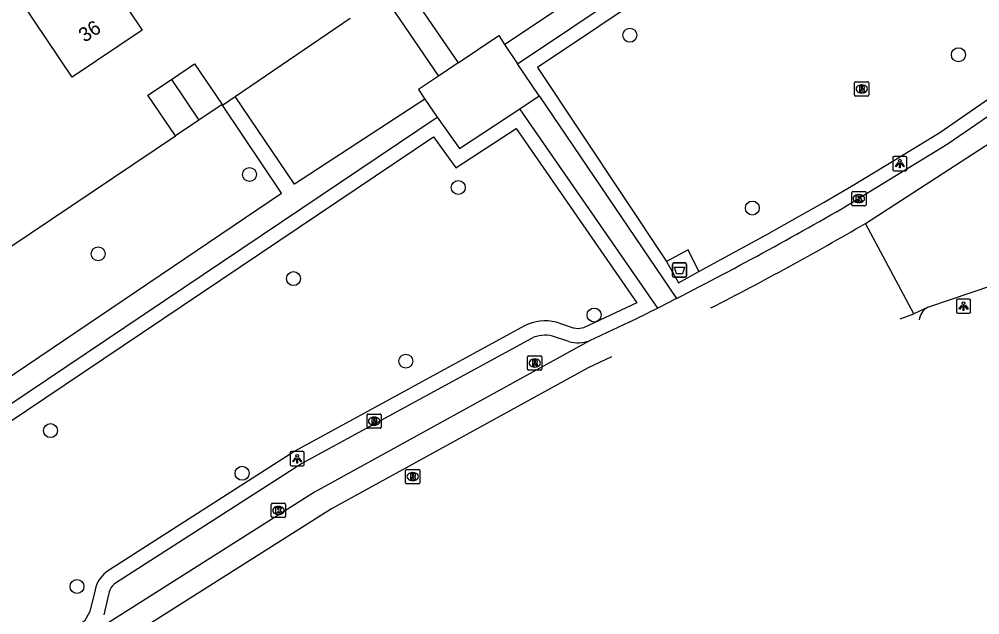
# Model space of a CAD drawing. Extents: x 158797 to 159887, y 384318 to 385255.
# Drawn here: x 159229 to 159296.2, y 384495.3 to 384536.9 of the extents above; entities that cross this region are included whole.
import ezdxf

# ---------------------------------------------------------------- set-up
doc = ezdxf.new("R2010")
doc.units = 0
for name, color, linetype in [('IMGEO_Afval_apart_plaats', 7, 'Continuous'), ('IMGEO_Boom', 7, 'Continuous'), ('IMGEO_Fietspad_gesloten', 7, 'Continuous'), ('IMGEO_Groenvoorziening', 7, 'Continuous'), ('IMGEO_Kolk', 7, 'Continuous'), ('IMGEO_Lichtpunt', 7, 'Continuous'), ('IMGEO_Pand', 7, 'Continuous'), ('IMGEO_Pand_nummerreeks', 7, 'Continuous'), ('IMGEO_Parkeervlak_open', 7, 'Continuous'), ('IMGEO_Rijbaan_lokaal_gesloten', 7, 'Continuous'), ('IMGEO_Rioolput', 7, 'Continuous'), ('IMGEO_Voetpad_gesloten', 7, 'Continuous'), ('IMGEO_Voetpad_open', 7, 'Continuous')]:
    doc.layers.add(name, color=color, linetype=linetype)

msp = doc.modelspace()

# ---------------------------------------------------------------- linework, layer by layer
at = {"layer": 'IMGEO_Afval_apart_plaats'}
for p, q in [((159274.727, 384518.982), (159274.727, 384519.782)), ((159274.727, 384519.782), (159274.727, 384518.982)), ((159274.827, 384519.882), (159275.617, 384519.882)), ((159275.617, 384519.882), (159274.827, 384519.882)), ((159275.717, 384519.782), (159275.717, 384518.982)), ((159275.717, 384518.982), (159275.717, 384519.782)), ((159275.617, 384518.882), (159274.827, 384518.882)), ((159274.827, 384518.882), (159275.617, 384518.882))]:
    msp.add_line(p, q, dxfattribs=at)
msp.add_lwpolyline([(159274.87, 384519.596), (159275.574, 384519.596), (159275.425, 384519.126), (159275.019, 384519.126), (159274.87, 384519.596)], dxfattribs=at)
for centre, start, end in [((159274.827, 384519.782), 90, 180), ((159274.827, 384519.782), 90, 180), ((159275.617, 384519.782), 0, 90), ((159275.617, 384519.782), 360, 90), ((159274.827, 384518.982), 180, 270), ((159274.827, 384518.982), 180, 270), ((159275.617, 384518.982), 270, 0), ((159275.617, 384518.982), 270, 0)]:
    msp.add_arc(centre, 0.1, start, end, dxfattribs=at)
at = {"layer": 'IMGEO_Boom'}
for centre in [(159271.748, 384535.8), (159294.74, 384534.44), (159245.143, 384526.065), (159259.751, 384525.162), (159280.321, 384523.725), (159234.56, 384520.524), (159248.224, 384518.788), (159269.249, 384516.243), (159256.083, 384513.017), (159231.225, 384508.163), (159244.626, 384505.181), (159233.077, 384497.268)]:
    msp.add_circle(centre, 0.489, dxfattribs=at)
at = {"layer": 'IMGEO_Fietspad_gesloten'}
msp.add_arc((159293.085, 384515.816), 1.088, 175.5911, 175.6123, dxfattribs=at)
at = {"layer": 'IMGEO_Groenvoorziening'}
for points in [[(159311.177, 384564.219), (159308.412, 384562.373), (159265.287, 384533.543), (159274.314, 384519.978)], [(159276.571, 384519.282), (159281.338, 384521.882), (159283.111, 384522.865), (159285.343, 384524.129), (159287.269, 384525.243), (159290.444, 384527.181), (159293.442, 384529.011), (159297.442, 384531.774), (159302.72, 384535.661), (159311.813, 384541.934), (159311.436, 384543.505), (159312.412, 384557.941)], [(159244.137, 384531.512), (159252.189, 384536.989)], [(159243.228, 384530.957), (159243.246, 384530.917)], [(159234.338, 384497.035), (159233.972, 384495.518), (159233.613, 384494.852), (159228.138, 384491.231), (159220.064, 384503.217), (159258.024, 384528.696), (159259.578, 384526.528), (159263.801, 384529.281), (159272.238, 384517.091), (159268.503, 384515.357), (159268.144, 384515.272), (159267.81, 384515.334), (159266.587, 384515.738)], [(159226.859, 384519.981), (159239.965, 384528.766)], [(159264.392, 384515.484), (159248.322, 384506.725), (159235.289, 384498.386)]]:
    msp.add_lwpolyline(points, dxfattribs=at)
for centre, radius, start, end in [((159265.818, 384512.772), 3.064, 75.46792, 117.73361), ((159236.374, 384496.612), 2.079, 121.44672, 168.26808)]:
    msp.add_arc(centre, radius, start, end, dxfattribs=at)
at = {"layer": 'IMGEO_Kolk'}
for p, q in [((159287.273, 384523.954), (159287.273, 384524.806)), ((159287.348, 384524.88), (159288.2, 384524.88)), ((159287.761, 384524.66), (159287.786, 384524.66)), ((159288.274, 384524.806), (159288.274, 384523.954)), ((159288.2, 384523.88), (159287.348, 384523.88)), ((159287.784, 384524.1), (159287.759, 384524.1)), ((159246.672, 384502.157), (159246.672, 384503.009)), ((159246.747, 384503.083), (159247.599, 384503.083)), ((159247.16, 384502.863), (159247.185, 384502.863)), ((159247.673, 384503.009), (159247.673, 384502.157)), ((159247.183, 384502.303), (159247.158, 384502.303)), ((159247.599, 384502.083), (159246.747, 384502.083))]:
    msp.add_line(p, q, dxfattribs=at)
for points in [[(159287.273, 384523.954), (159287.273, 384524.806)], [(159287.348, 384524.88), (159288.2, 384524.88)], [(159287.594, 384524.58), (159287.717, 384524.58), (159287.717, 384524.429), (159287.847, 384524.58), (159288.011, 384524.58), (159287.865, 384524.429), (159288.018, 384524.18), (159287.866, 384524.18), (159287.781, 384524.344), (159287.717, 384524.277), (159287.717, 384524.18), (159287.594, 384524.18), (159287.594, 384524.58)], [(159288.274, 384524.806), (159288.274, 384523.954)], [(159288.2, 384523.88), (159287.348, 384523.88)], [(159246.672, 384502.157), (159246.672, 384503.009)], [(159246.747, 384503.083), (159247.599, 384503.083)], [(159246.993, 384502.783), (159247.116, 384502.783), (159247.116, 384502.632), (159247.246, 384502.783), (159247.41, 384502.783), (159247.264, 384502.632), (159247.417, 384502.383), (159247.265, 384502.383), (159247.18, 384502.547), (159247.116, 384502.48), (159247.116, 384502.383), (159246.993, 384502.383), (159246.993, 384502.783)], [(159247.673, 384503.009), (159247.673, 384502.157)], [(159247.599, 384502.083), (159246.747, 384502.083)]]:
    msp.add_lwpolyline(points, dxfattribs=at)
for centre, start, end in [((159287.35, 384524.804), 91.55205, 178.44795), ((159287.35, 384524.804), 91.55205, 178.44795), ((159288.198, 384524.804), 1.55205, 88.44795), ((159288.198, 384524.804), 1.55205, 88.44795), ((159287.35, 384523.956), 181.55205, 268.44795), ((159287.35, 384523.956), 181.55205, 268.44795), ((159288.198, 384523.956), 271.55205, 358.44795), ((159288.198, 384523.956), 271.55205, 358.44795), ((159246.749, 384503.007), 91.55205, 178.44795), ((159246.749, 384503.007), 91.55205, 178.44795), ((159247.597, 384503.007), 1.55205, 88.44795), ((159247.597, 384503.007), 1.55205, 88.44795), ((159246.749, 384502.159), 181.55205, 268.44795), ((159246.749, 384502.159), 181.55205, 268.44795), ((159247.597, 384502.159), 271.55205, 358.44795), ((159247.597, 384502.159), 271.55205, 358.44795)]:
    msp.add_arc(centre, 0.0765, start, end, dxfattribs=at)
for centre, major_axis, ratio, start_param, end_param in [((159287.76, 384524.38), (-0.387, 0.002), 0.722429, 4.712389, 7.853982), ((159287.785, 384524.38), (-0.39, 0.002), 0.717154, 1.570796, 4.712389), ((159247.159, 384502.583), (-0.387, 0.002), 0.722429, 4.712389, 7.853982), ((159247.184, 384502.583), (-0.39, 0.002), 0.717154, 1.570796, 4.712389)]:
    msp.add_ellipse(centre, major_axis=major_axis, ratio=ratio, start_param=start_param, end_param=end_param, dxfattribs=at)
at = {"layer": 'IMGEO_Lichtpunt'}
for p, q in [((159290.139, 384527.233), (159290.139, 384526.426)), ((159290.139, 384527.233), (159290.139, 384526.426)), ((159291.041, 384527.328), (159290.233, 384527.328)), ((159291.041, 384527.328), (159290.233, 384527.328)), ((159291.135, 384526.426), (159291.135, 384527.233)), ((159291.135, 384526.426), (159291.135, 384527.233)), ((159290.233, 384526.332), (159291.041, 384526.332)), ((159290.233, 384526.332), (159291.041, 384526.332)), ((159294.599, 384517.266), (159294.599, 384516.459)), ((159294.599, 384517.266), (159294.599, 384516.459)), ((159295.501, 384517.361), (159294.693, 384517.361)), ((159295.501, 384517.361), (159294.693, 384517.361)), ((159295.595, 384516.459), (159295.595, 384517.266)), ((159295.595, 384516.459), (159295.595, 384517.266)), ((159294.693, 384516.365), (159295.501, 384516.365)), ((159294.693, 384516.365), (159295.501, 384516.365)), ((159247.979, 384506.604), (159247.979, 384505.797)), ((159247.979, 384506.604), (159247.979, 384505.797)), ((159248.881, 384506.699), (159248.073, 384506.699)), ((159248.881, 384506.699), (159248.073, 384506.699)), ((159248.975, 384505.797), (159248.975, 384506.604)), ((159248.975, 384505.797), (159248.975, 384506.604)), ((159248.073, 384505.703), (159248.881, 384505.703)), ((159248.073, 384505.703), (159248.881, 384505.703))]:
    msp.add_line(p, q, dxfattribs=at)
for points in [[(159290.513, 384526.897), (159290.552, 384526.869), (159290.364, 384526.607), (159290.326, 384526.634), (159290.513, 384526.897)], [(159290.615, 384526.849), (159290.662, 384526.849), (159290.662, 384526.527), (159290.615, 384526.527), (159290.615, 384526.849)], [(159290.725, 384526.869), (159290.763, 384526.896), (159290.95, 384526.634), (159290.911, 384526.606), (159290.725, 384526.869)], [(159294.973, 384516.93), (159295.012, 384516.902), (159294.824, 384516.64), (159294.786, 384516.667), (159294.973, 384516.93)], [(159295.185, 384516.902), (159295.223, 384516.929), (159295.41, 384516.667), (159295.371, 384516.639), (159295.185, 384516.902)], [(159295.075, 384516.882), (159295.122, 384516.882), (159295.122, 384516.56), (159295.075, 384516.56), (159295.075, 384516.882)], [(159248.353, 384506.268), (159248.392, 384506.24), (159248.204, 384505.978), (159248.166, 384506.005), (159248.353, 384506.268)], [(159248.455, 384506.22), (159248.502, 384506.22), (159248.502, 384505.898), (159248.455, 384505.898), (159248.455, 384506.22)], [(159248.565, 384506.24), (159248.603, 384506.267), (159248.79, 384506.005), (159248.751, 384505.977), (159248.565, 384506.24)]]:
    msp.add_lwpolyline(points, dxfattribs=at)
for centre in [(159290.638, 384527.031), (159295.098, 384517.064), (159248.478, 384506.402)]:
    msp.add_circle(centre, 0.0994, dxfattribs=at)
for centre, start, end in [((159290.233, 384527.233), 90, 180), ((159290.233, 384527.233), 90, 180), ((159291.041, 384527.233), 0, 90), ((159291.041, 384527.233), 0, 90), ((159290.233, 384526.426), 180, 270), ((159290.233, 384526.426), 180, 270), ((159291.041, 384526.426), 270, 0), ((159291.041, 384526.426), 270, 360), ((159294.693, 384517.266), 90, 180), ((159294.693, 384517.266), 90, 180), ((159295.501, 384517.266), 0, 90), ((159295.501, 384517.266), 0, 90), ((159294.693, 384516.459), 180, 270), ((159294.693, 384516.459), 180, 270), ((159295.501, 384516.459), 270, 0), ((159295.501, 384516.459), 270, 360), ((159248.073, 384506.604), 90, 180), ((159248.073, 384506.604), 90, 180), ((159248.881, 384506.604), 0, 90), ((159248.881, 384506.604), 0, 90), ((159248.073, 384505.797), 180, 270), ((159248.073, 384505.797), 180, 270), ((159248.881, 384505.797), 270, 0), ((159248.881, 384505.797), 270, 360)]:
    msp.add_arc(centre, 0.0946, start, end, dxfattribs=at)
at = {"layer": 'IMGEO_Pand'}
for points in [[(159236.634, 384537.647), (159237.641, 384536.151), (159232.743, 384532.872), (159228.326, 384539.445), (159227.823, 384539.108), (159225.578, 384542.461), (159228.603, 384544.487), (159228.94, 384543.985), (159231.299, 384545.572)], [(159239.679, 384532.717), (159241.305, 384533.807), (159243.228, 384530.957)], [(159239.965, 384528.766), (159238.042, 384531.62), (159239.679, 384532.717)], [(159239.679, 384532.717), (159241.597, 384529.862)], [(159243.228, 384530.957), (159241.597, 384529.862)], [(159241.597, 384529.862), (159239.965, 384528.766)]]:
    msp.add_lwpolyline(points, dxfattribs=at)
at = {"layer": 'IMGEO_Parkeervlak_open'}
for points in [[(159264.87, 384514.606), (159248.861, 384505.883), (159235.764, 384497.503)], [(159267.494, 384514.385), (159266.337, 384514.77)], [(159235.31, 384496.8), (159234.944, 384495.283)]]:
    msp.add_lwpolyline(points, dxfattribs=at)
for centre, radius, start, end in [((159265.819, 384512.764), 2.072, 75.5149, 117.24264), ((159268.107, 384516.654), 2.351, 254.87595, 290.32917), ((159236.383, 384496.605), 1.09, 124.57769, 169.71327)]:
    msp.add_arc(centre, radius, start, end, dxfattribs=at)
at = {"layer": 'IMGEO_Rijbaan_lokaal_gesloten'}
for points in [[(159303.313, 384534.856), (159298.035, 384530.969), (159293.963, 384528.157), (159287.774, 384524.38)], [(159288.239, 384522.647), (159304.461, 384533.157)], [(159291.62, 384516.319), (159288.239, 384522.647)], [(159300.224, 384519.358), (159292.566, 384516.771)], [(159275.021, 384517.404), (159273.701, 384516.735)], [(159290.652, 384515.977), (159291.62, 384516.319)], [(159292.566, 384516.771), (159291.62, 384516.319)], [(159271.696, 384515.737), (159268.924, 384514.45)], [(159292, 384515.9), (159292, 384515.9)], [(159268.924, 384514.45), (159249.7, 384503.863), (159234.165, 384494.018)], [(159270.461, 384513.33), (159268.841, 384512.562), (159250.873, 384502.69), (159237.802, 384494.419), (159214.07, 384478.627), (159115.99, 384412.992)]]:
    msp.add_lwpolyline(points, dxfattribs=at)
for centre, radius, start, end in [((159158.359, 384745.821), 256.485, 297.0552, 300.30287), ((159175.471, 384716.26), 224.059, 297.0671, 300.21836), ((159180.412, 384701.641), 207.106, 296.15228, 296.77188), ((159293.08, 384515.817), 1.084, 118.34326, 175.62288)]:
    msp.add_arc(centre, radius, start, end, dxfattribs=at)
at = {"layer": 'IMGEO_Rioolput'}
for p, q in [((159287.475, 384531.625), (159287.475, 384532.477)), ((159287.55, 384532.551), (159288.402, 384532.551)), ((159288.476, 384532.477), (159288.476, 384531.625)), ((159287.986, 384531.771), (159287.961, 384531.771)), ((159287.963, 384532.331), (159287.988, 384532.331)), ((159288.402, 384531.551), (159287.55, 384531.551)), ((159264.599, 384512.459), (159264.599, 384513.311)), ((159264.674, 384513.385), (159265.526, 384513.385)), ((159265.087, 384513.165), (159265.112, 384513.165)), ((159265.6, 384513.311), (159265.6, 384512.459)), ((159265.526, 384512.385), (159264.674, 384512.385)), ((159265.11, 384512.605), (159265.085, 384512.605)), ((159253.365, 384508.399), (159253.365, 384509.251)), ((159253.44, 384509.325), (159254.292, 384509.325)), ((159253.853, 384509.105), (159253.878, 384509.105)), ((159254.366, 384509.251), (159254.366, 384508.399)), ((159254.292, 384508.325), (159253.44, 384508.325)), ((159253.876, 384508.545), (159253.851, 384508.545)), ((159256.061, 384504.526), (159256.061, 384505.378)), ((159256.136, 384505.452), (159256.988, 384505.452)), ((159256.549, 384505.232), (159256.574, 384505.232)), ((159257.062, 384505.378), (159257.062, 384504.526)), ((159256.988, 384504.452), (159256.136, 384504.452)), ((159256.572, 384504.672), (159256.547, 384504.672))]:
    msp.add_line(p, q, dxfattribs=at)
for points in [[(159287.475, 384531.625), (159287.475, 384532.477)], [(159287.55, 384532.551), (159288.402, 384532.551)], [(159288.476, 384532.477), (159288.476, 384531.625)], [(159288.064, 384532.249), (159287.812, 384532.251), (159287.812, 384531.851)], [(159287.812, 384531.851), (159287.936, 384531.851), (159287.936, 384532.013), (159287.947, 384532.013)], [(159287.99, 384532.17), (159287.936, 384532.17), (159287.936, 384532.089)], [(159287.936, 384532.089), (159287.988, 384532.089)], [(159287.994, 384531.984), (159288.065, 384531.851), (159288.205, 384531.851), (159288.14, 384531.977)], [(159288.402, 384531.551), (159287.55, 384531.551)], [(159264.599, 384512.459), (159264.599, 384513.311)], [(159264.674, 384513.385), (159265.526, 384513.385)], [(159265.188, 384513.083), (159264.936, 384513.085), (159264.936, 384512.685)], [(159265.114, 384513.004), (159265.06, 384513.004), (159265.06, 384512.923)], [(159265.06, 384512.923), (159265.112, 384512.923)], [(159265.6, 384513.311), (159265.6, 384512.459)], [(159265.526, 384512.385), (159264.674, 384512.385)], [(159264.936, 384512.685), (159265.06, 384512.685), (159265.06, 384512.847), (159265.071, 384512.847)], [(159265.118, 384512.818), (159265.189, 384512.685), (159265.329, 384512.685), (159265.264, 384512.811)], [(159253.365, 384508.399), (159253.365, 384509.251)], [(159253.44, 384509.325), (159254.292, 384509.325)], [(159253.954, 384509.023), (159253.702, 384509.025), (159253.702, 384508.625)], [(159253.88, 384508.944), (159253.826, 384508.944), (159253.826, 384508.863)], [(159253.826, 384508.863), (159253.878, 384508.863)], [(159254.366, 384509.251), (159254.366, 384508.399)], [(159254.292, 384508.325), (159253.44, 384508.325)], [(159253.702, 384508.625), (159253.826, 384508.625), (159253.826, 384508.787), (159253.837, 384508.787)], [(159253.884, 384508.758), (159253.955, 384508.625), (159254.095, 384508.625), (159254.03, 384508.751)], [(159256.061, 384504.526), (159256.061, 384505.378)], [(159256.136, 384505.452), (159256.988, 384505.452)], [(159256.65, 384505.15), (159256.398, 384505.152), (159256.398, 384504.752)], [(159256.398, 384504.752), (159256.522, 384504.752), (159256.522, 384504.914), (159256.533, 384504.914)], [(159256.576, 384505.071), (159256.522, 384505.071), (159256.522, 384504.99)], [(159256.522, 384504.99), (159256.574, 384504.99)], [(159256.58, 384504.885), (159256.651, 384504.752), (159256.791, 384504.752), (159256.726, 384504.878)], [(159257.062, 384505.378), (159257.062, 384504.526)], [(159256.988, 384504.452), (159256.136, 384504.452)]]:
    msp.add_lwpolyline(points, dxfattribs=at)
for centre, radius, start, end in [((159287.552, 384532.475), 0.0765, 91.55205, 178.44795), ((159287.552, 384532.475), 0.0765, 91.55205, 178.44795), ((159288.4, 384532.475), 0.0765, 1.55205, 88.44795), ((159288.4, 384532.475), 0.0765, 1.55205, 88.44795), ((159287.946, 384531.96), 0.0533, 26.02933, 88.69889), ((159287.972, 384532.278), 0.19, 274.7715, 282.96867), ((159287.996, 384532.074), 0.0964, 77.00612, 93.18647), ((159288.01, 384532.131), 0.0378, 276.66336, 79.67722), ((159288.063, 384532.139), 0.109, 350.36119, 89.41601), ((159288.061, 384532.139), 0.112, 277.58423, 350.98172), ((159288.045, 384531.924), 0.108, 29.51342, 73.79051), ((159287.552, 384531.627), 0.0765, 181.55205, 268.44795), ((159287.552, 384531.627), 0.0765, 181.55205, 268.44795), ((159288.4, 384531.627), 0.0765, 271.55205, 358.44795), ((159288.4, 384531.627), 0.0765, 271.55205, 358.44795), ((159264.676, 384513.309), 0.0765, 91.55205, 178.44795), ((159264.676, 384513.309), 0.0765, 91.55205, 178.44795), ((159265.096, 384513.112), 0.19, 274.7715, 282.96867), ((159265.12, 384512.908), 0.0964, 77.00612, 93.18647), ((159265.134, 384512.965), 0.0378, 276.66336, 79.67722), ((159265.187, 384512.973), 0.109, 350.36119, 89.41601), ((159265.185, 384512.973), 0.112, 277.58423, 350.98172), ((159265.169, 384512.758), 0.108, 29.51342, 73.79051), ((159265.524, 384513.309), 0.0765, 1.55205, 88.44795), ((159265.524, 384513.309), 0.0765, 1.55205, 88.44795), ((159264.676, 384512.461), 0.0765, 181.55205, 268.44795), ((159264.676, 384512.461), 0.0765, 181.55205, 268.44795), ((159265.07, 384512.794), 0.0533, 26.02933, 88.69889), ((159265.524, 384512.461), 0.0765, 271.55205, 358.44795), ((159265.524, 384512.461), 0.0765, 271.55205, 358.44795), ((159253.442, 384509.249), 0.0765, 91.55205, 178.44795), ((159253.442, 384509.249), 0.0765, 91.55205, 178.44795), ((159253.862, 384509.052), 0.19, 274.7715, 282.96867), ((159253.886, 384508.848), 0.0964, 77.00612, 93.18647), ((159253.9, 384508.905), 0.0378, 276.66336, 79.67722), ((159253.953, 384508.913), 0.109, 350.36119, 89.41601), ((159253.951, 384508.913), 0.112, 277.58423, 350.98172), ((159254.29, 384509.249), 0.0765, 1.55205, 88.44795), ((159254.29, 384509.249), 0.0765, 1.55205, 88.44795), ((159253.442, 384508.401), 0.0765, 181.55205, 268.44795), ((159253.442, 384508.401), 0.0765, 181.55205, 268.44795), ((159253.836, 384508.734), 0.0533, 26.02933, 88.69889), ((159253.935, 384508.698), 0.108, 29.51342, 73.79051), ((159254.29, 384508.401), 0.0765, 271.55205, 358.44795), ((159254.29, 384508.401), 0.0765, 271.55205, 358.44795), ((159256.138, 384505.376), 0.0765, 91.55205, 178.44795), ((159256.138, 384505.376), 0.0765, 91.55205, 178.44795), ((159256.532, 384504.861), 0.0533, 26.02933, 88.69889), ((159256.558, 384505.179), 0.19, 274.7715, 282.96867), ((159256.582, 384504.975), 0.0964, 77.00612, 93.18647), ((159256.596, 384505.032), 0.0378, 276.66336, 79.67722), ((159256.649, 384505.04), 0.109, 350.36119, 89.41601), ((159256.647, 384505.04), 0.112, 277.58423, 350.98172), ((159256.631, 384504.825), 0.108, 29.51342, 73.79051), ((159256.986, 384505.376), 0.0765, 1.55205, 88.44795), ((159256.986, 384505.376), 0.0765, 1.55205, 88.44795), ((159256.138, 384504.528), 0.0765, 181.55205, 268.44795), ((159256.138, 384504.528), 0.0765, 181.55205, 268.44795), ((159256.986, 384504.528), 0.0765, 271.55205, 358.44795), ((159256.986, 384504.528), 0.0765, 271.55205, 358.44795)]:
    msp.add_arc(centre, radius, start, end, dxfattribs=at)
for centre, major_axis, ratio, start_param, end_param in [((159287.962, 384532.051), (-0.387, 0.002), 0.722429, 4.712389, 7.853982), ((159287.987, 384532.051), (-0.39, 0.002), 0.717154, 1.570796, 4.712389), ((159265.086, 384512.885), (-0.387, 0.002), 0.722429, 4.712389, 7.853982), ((159265.111, 384512.885), (-0.39, 0.002), 0.717154, 1.570796, 4.712389), ((159253.852, 384508.825), (-0.387, 0.002), 0.722429, 4.712389, 7.853982), ((159253.877, 384508.825), (-0.39, 0.002), 0.717154, 1.570796, 4.712389), ((159256.548, 384504.952), (-0.387, 0.002), 0.722429, 4.712389, 7.853982), ((159256.573, 384504.952), (-0.39, 0.002), 0.717154, 1.570796, 4.712389)]:
    msp.add_ellipse(centre, major_axis=major_axis, ratio=ratio, start_param=start_param, end_param=end_param, dxfattribs=at)
at = {"layer": 'IMGEO_Voetpad_gesloten'}
for points in [[(159262.993, 384535.164), (159312.028, 384567.885), (159313.543, 384565.466)], [(159263.888, 384533.81), (159311.453, 384565.609)], [(159252.893, 384543.878), (159259.749, 384533.873)], [(159252.602, 384541.404), (159258.358, 384532.95)], [(159262.993, 384535.164), (159263.888, 384533.81)], [(159259.749, 384533.873), (159258.358, 384532.95)], [(159243.246, 384530.917), (159244.137, 384531.512)], [(159257.407, 384531.328), (159248.3, 384525.386), (159244.137, 384531.512)], [(159257.407, 384531.328), (159258.272, 384530.067)], [(159264.068, 384530.653), (159265.419, 384531.565)], [(159265.419, 384531.565), (159275.021, 384517.404)], [(159217.766, 384504.842), (159226.837, 384510.895), (159222.724, 384516.979), (159223.652, 384517.648), (159227.883, 384511.597), (159247.382, 384524.762), (159243.246, 384530.917)], [(159273.701, 384516.735), (159264.068, 384530.653)], [(159218.685, 384503.496), (159258.272, 384530.067)], [(159276.571, 384519.282), (159275.841, 384520.81), (159274.314, 384519.978)], [(159274.314, 384519.978), (159275.153, 384518.498), (159276.571, 384519.282)]]:
    msp.add_lwpolyline(points, dxfattribs=at)
at = {"layer": 'IMGEO_Voetpad_open'}
for points in [[(159259.749, 384533.873), (159262.59, 384535.774), (159262.993, 384535.164)], [(159265.419, 384531.565), (159263.888, 384533.81)], [(159258.358, 384532.95), (159256.967, 384532.01), (159257.407, 384531.328)], [(159258.272, 384530.067), (159259.833, 384527.888), (159264.068, 384530.653)]]:
    msp.add_lwpolyline(points, dxfattribs=at)

# ---------------------------------------------------------------- texts
at = {"layer": 'IMGEO_Pand_nummerreeks'}
msp.add_text('36', height=1, rotation=33.60397, dxfattribs=at).set_placement((159233.611, 384535.261))

doc.saveas('drawing.dxf')
